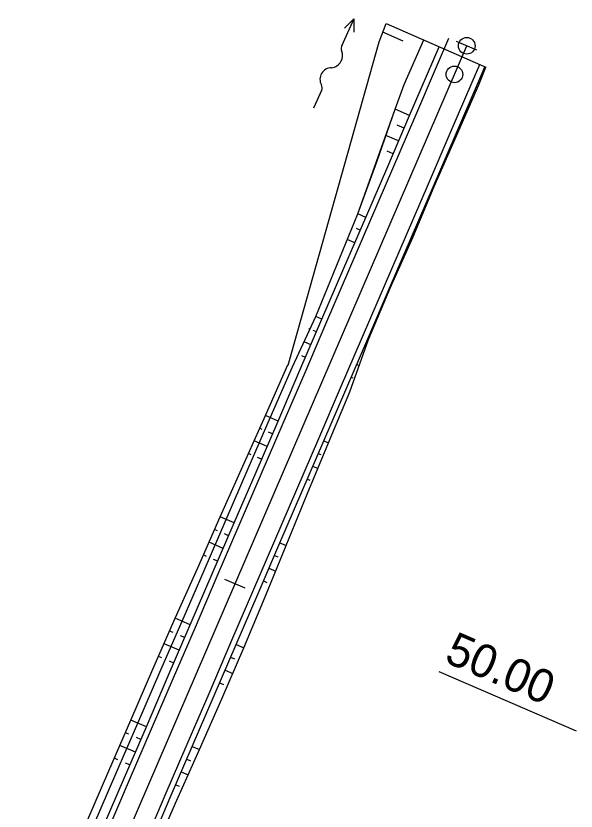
# Model space of a CAD drawing. Extents: x -481645 to -478728, y -1113199 to -1110710.
# Drawn here: x -480117.1 to -480066.6, y -1112436.3 to -1112364.6 of the extents above; entities that cross this region are included whole.
import ezdxf

# ---------------------------------------------------------------- set-up
doc = ezdxf.new("R2010")
doc.units = 0
for name, color, linetype in [('CP14_HECTOMETRY', 7, 'Continuous'), ('CP14_HLBODY', 7, 'Continuous'), ('Vrstva 52', 7, 'Continuous'), ('Vrstva 53', 7, 'Continuous'), ('Vrstva 54', 7, 'Continuous'), ('Vrstva 55', 7, 'Continuous'), ('Vrstva 56', 7, 'Continuous'), ('Vrstva 57', 7, 'Continuous'), ('Vrstva 58', 7, 'Continuous'), ('Vrstva 59', 7, 'Continuous'), ('Vrstva 60', 7, 'Continuous'), ('Vrstva 61', 7, 'Continuous'), ('Vrstva 62', 7, 'Continuous')]:
    doc.layers.add(name, color=color, linetype=linetype)

# ---------------------------------------------------------------- blocks, each defined once
blk = doc.blocks.new('A$C70B')
at = {"layer": 'CP14_HLBODY'}
for p, q in [((0.869, 0.002), (-0.869, -0.002)), ((6.861, 0.426), (7.971, -0.002)), ((7.971, -0.002), (5.275, -0.002)), ((7.971, -0.002), (6.862, -0.478))]:
    blk.add_line(p, q, dxfattribs=at)
for centre, radius, start, end in [((0.872, 0.584), 0.582, 269.69241, 322.79009), ((2.168, -0.416), 1.055, 24.40393, 142.08362), ((4.08, 0.589), 1.109, 210.88731, 317.37071), ((5.319, -0.636), 0.636, 85.97658, 131.72478)]:
    blk.add_arc(centre, radius, start, end, dxfattribs=at)

msp = doc.modelspace()

# ---------------------------------------------------------------- linework, layer by layer
at = {"layer": 'Vrstva 52'}
msp.add_line((-480117.117, -1112461.699), (-480076.44, -1112367.31), dxfattribs=at)
at = {"layer": 'Vrstva 53'}
for p, q in [((-480084.346, -1112366.961), (-480083.701, -1112365.308)), ((-480084.345, -1112366.962), (-480083.7, -1112365.308)), ((-480083.7, -1112365.308), (-480074.708, -1112369.248)), ((-480092.564, -1112396.087), (-480084.345, -1112366.962)), ((-480075.357, -1112370.835), (-480074.708, -1112369.248)), ((-480077.359, -1112375.417), (-480075.357, -1112370.835)), ((-480086.281, -1112382.461), (-480082.906, -1112373.026)), ((-480084.564, -1112377.756), (-480082.906, -1112373.026)), ((-480079.392, -1112379.985), (-480077.359, -1112375.417)), ((-480086.281, -1112382.461), (-480084.564, -1112377.756)), ((-480081.303, -1112384.606), (-480079.392, -1112379.985)), ((-480088.162, -1112387.095), (-480086.281, -1112382.461)), ((-480088.162, -1112387.095), (-480086.281, -1112382.461)), ((-480083.344, -1112389.171), (-480081.303, -1112384.606)), ((-480090.068, -1112391.718), (-480088.162, -1112387.095)), ((-480090.068, -1112391.718), (-480088.162, -1112387.095)), ((-480085.299, -1112393.773), (-480083.344, -1112389.171)), ((-480086.981, -1112398.493), (-480085.299, -1112393.773)), ((-480094.609, -1112400.65), (-480092.575, -1112396.082)), ((-480088.911, -1112403.106), (-480086.981, -1112398.493)), ((-480096.643, -1112405.218), (-480094.609, -1112400.65)), ((-480090.832, -1112407.722), (-480088.911, -1112403.106)), ((-480098.678, -1112409.785), (-480096.643, -1112405.218)), ((-480092.728, -1112412.35), (-480090.832, -1112407.722)), ((-480100.712, -1112414.354), (-480098.678, -1112409.785)), ((-480094.625, -1112416.976), (-480092.728, -1112412.35)), ((-480102.746, -1112418.921), (-480100.712, -1112414.354)), ((-480096.567, -1112421.584), (-480094.625, -1112416.976)), ((-480104.756, -1112423.499), (-480102.746, -1112418.921)), ((-480098.543, -1112426.177), (-480096.567, -1112421.584)), ((-480106.733, -1112428.092), (-480104.756, -1112423.499)), ((-480100.542, -1112430.76), (-480098.543, -1112426.177)), ((-480108.719, -1112432.681), (-480106.733, -1112428.092)), ((-480102.582, -1112435.326), (-480100.542, -1112430.76)), ((-480110.705, -1112437.27), (-480108.719, -1112432.681)), ((-480104.622, -1112439.891), (-480102.582, -1112435.326))]:
    msp.add_line(p, q, dxfattribs=at)
at = {"layer": 'Vrstva 54'}
for p, q in [((-480082.089, -1112370.811), (-480080.326, -1112366.786)), ((-480082.906, -1112373.026), (-480082.089, -1112370.811)), ((-480092.172, -1112396.255), (-480090.068, -1112391.718)), ((-480092.165, -1112396.258), (-480090.068, -1112391.718)), ((-480094.163, -1112400.842), (-480092.172, -1112396.255)), ((-480096.154, -1112405.428), (-480094.163, -1112400.842)), ((-480098.145, -1112410.015), (-480096.154, -1112405.428)), ((-480100.136, -1112414.601), (-480098.145, -1112410.015)), ((-480102.127, -1112419.188), (-480100.136, -1112414.601)), ((-480104.118, -1112423.775), (-480102.127, -1112419.188)), ((-480106.109, -1112428.361), (-480104.118, -1112423.775)), ((-480108.1, -1112432.948), (-480106.109, -1112428.361)), ((-480110.091, -1112437.534), (-480108.1, -1112432.948))]:
    msp.add_line(p, q, dxfattribs=at)
at = {"layer": 'Vrstva 55'}
for p, q in [((-480081.597, -1112373.59), (-480078.928, -1112367.399)), ((-480079.618, -1112368.999), (-480079.486, -1112368.692)), ((-480075.485, -1112370.78), (-480074.806, -1112369.204)), ((-480077.464, -1112375.371), (-480075.485, -1112370.78)), ((-480083.575, -1112378.182), (-480081.597, -1112373.59)), ((-480079.443, -1112379.963), (-480077.464, -1112375.371)), ((-480085.554, -1112382.774), (-480083.575, -1112378.182)), ((-480081.422, -1112384.555), (-480079.443, -1112379.963)), ((-480087.533, -1112387.366), (-480085.554, -1112382.774)), ((-480083.4, -1112389.147), (-480081.422, -1112384.555)), ((-480089.512, -1112391.957), (-480087.533, -1112387.366)), ((-480085.379, -1112393.738), (-480083.4, -1112389.147)), ((-480091.491, -1112396.549), (-480089.512, -1112391.957)), ((-480087.358, -1112398.33), (-480085.379, -1112393.738)), ((-480093.469, -1112401.141), (-480091.491, -1112396.549)), ((-480089.337, -1112402.922), (-480087.358, -1112398.33)), ((-480095.448, -1112405.733), (-480093.469, -1112401.141)), ((-480091.316, -1112407.514), (-480089.337, -1112402.922)), ((-480097.427, -1112410.324), (-480095.448, -1112405.733)), ((-480093.294, -1112412.105), (-480091.316, -1112407.514)), ((-480099.406, -1112414.916), (-480097.427, -1112410.324)), ((-480095.273, -1112416.697), (-480093.294, -1112412.105)), ((-480101.385, -1112419.508), (-480099.406, -1112414.916)), ((-480097.252, -1112421.289), (-480095.273, -1112416.697)), ((-480103.364, -1112424.1), (-480101.385, -1112419.508)), ((-480099.231, -1112425.881), (-480097.252, -1112421.289)), ((-480105.342, -1112428.692), (-480103.364, -1112424.1)), ((-480101.21, -1112430.472), (-480099.231, -1112425.881)), ((-480107.321, -1112433.283), (-480105.342, -1112428.692)), ((-480103.189, -1112435.064), (-480101.21, -1112430.472)), ((-480109.3, -1112437.875), (-480107.321, -1112433.283)), ((-480105.167, -1112439.656), (-480103.189, -1112435.064))]:
    msp.add_line(p, q, dxfattribs=at)
at = {"layer": 'Vrstva 56'}
for p, q in [((-480079.159, -1112369.196), (-480078.05, -1112366.625)), ((-480081.137, -1112373.788), (-480079.159, -1112369.196)), ((-480075.944, -1112370.582), (-480075.264, -1112369.004)), ((-480077.923, -1112375.173), (-480075.944, -1112370.582)), ((-480083.116, -1112378.38), (-480081.137, -1112373.788)), ((-480079.902, -1112379.765), (-480077.923, -1112375.173)), ((-480085.095, -1112382.972), (-480083.116, -1112378.38)), ((-480081.881, -1112384.357), (-480079.902, -1112379.765)), ((-480087.074, -1112387.564), (-480085.095, -1112382.972)), ((-480083.86, -1112388.949), (-480081.881, -1112384.357)), ((-480089.053, -1112392.155), (-480087.074, -1112387.564)), ((-480085.838, -1112393.54), (-480083.86, -1112388.949)), ((-480091.031, -1112396.747), (-480089.053, -1112392.155)), ((-480087.817, -1112398.132), (-480085.838, -1112393.54)), ((-480093.01, -1112401.339), (-480091.031, -1112396.747)), ((-480089.796, -1112402.724), (-480087.817, -1112398.132)), ((-480094.989, -1112405.931), (-480093.01, -1112401.339)), ((-480091.775, -1112407.316), (-480089.796, -1112402.724)), ((-480096.968, -1112410.522), (-480094.989, -1112405.931)), ((-480093.754, -1112411.908), (-480091.775, -1112407.316)), ((-480098.947, -1112415.114), (-480096.968, -1112410.522)), ((-480095.732, -1112416.499), (-480093.754, -1112411.908)), ((-480100.926, -1112419.706), (-480098.947, -1112415.114)), ((-480097.711, -1112421.091), (-480095.732, -1112416.499)), ((-480102.904, -1112424.298), (-480100.926, -1112419.706)), ((-480099.69, -1112425.683), (-480097.711, -1112421.091)), ((-480104.883, -1112428.889), (-480102.904, -1112424.298)), ((-480101.669, -1112430.275), (-480099.69, -1112425.683)), ((-480106.862, -1112433.481), (-480104.883, -1112428.889)), ((-480103.648, -1112434.866), (-480101.669, -1112430.275)), ((-480108.841, -1112438.073), (-480106.862, -1112433.481)), ((-480105.627, -1112439.458), (-480103.648, -1112434.866))]:
    msp.add_line(p, q, dxfattribs=at)
at = {"layer": 'Vrstva 57'}
for p, q in [((-480079.159, -1112369.196), (-480078.05, -1112366.625)), ((-480081.137, -1112373.788), (-480079.159, -1112369.196)), ((-480075.944, -1112370.582), (-480075.264, -1112369.004)), ((-480077.923, -1112375.173), (-480075.944, -1112370.582)), ((-480083.116, -1112378.38), (-480081.137, -1112373.788)), ((-480079.902, -1112379.765), (-480077.923, -1112375.173)), ((-480085.095, -1112382.972), (-480083.116, -1112378.38)), ((-480081.881, -1112384.357), (-480079.902, -1112379.765)), ((-480087.074, -1112387.564), (-480085.095, -1112382.972)), ((-480083.86, -1112388.949), (-480081.881, -1112384.357)), ((-480089.053, -1112392.155), (-480087.074, -1112387.564)), ((-480085.838, -1112393.54), (-480083.86, -1112388.949)), ((-480091.031, -1112396.747), (-480089.053, -1112392.155)), ((-480087.817, -1112398.132), (-480085.838, -1112393.54)), ((-480093.01, -1112401.339), (-480091.031, -1112396.747)), ((-480089.796, -1112402.724), (-480087.817, -1112398.132)), ((-480094.989, -1112405.931), (-480093.01, -1112401.339)), ((-480091.775, -1112407.316), (-480089.796, -1112402.724)), ((-480096.968, -1112410.522), (-480094.989, -1112405.931)), ((-480093.754, -1112411.908), (-480091.775, -1112407.316)), ((-480098.947, -1112415.114), (-480096.968, -1112410.522)), ((-480095.732, -1112416.499), (-480093.754, -1112411.908)), ((-480100.926, -1112419.706), (-480098.947, -1112415.114)), ((-480097.711, -1112421.091), (-480095.732, -1112416.499)), ((-480102.904, -1112424.298), (-480100.926, -1112419.706)), ((-480099.69, -1112425.683), (-480097.711, -1112421.091)), ((-480104.883, -1112428.889), (-480102.904, -1112424.298)), ((-480101.669, -1112430.275), (-480099.69, -1112425.683)), ((-480106.862, -1112433.481), (-480104.883, -1112428.889)), ((-480103.648, -1112434.866), (-480101.669, -1112430.275)), ((-480108.841, -1112438.073), (-480106.862, -1112433.481)), ((-480105.627, -1112439.458), (-480103.648, -1112434.866))]:
    msp.add_line(p, q, dxfattribs=at)
at = {"layer": 'Vrstva 58'}
for p, q in [((-480075.525, -1112367.713), (-480077.362, -1112366.922)), ((-480096.421, -1112416.202), (-480098.258, -1112415.411)), ((-480078.973, -1112423.722), (-480066.575, -1112429.065))]:
    msp.add_line(p, q, dxfattribs=at)
at = {"layer": 'Vrstva 59'}
msp.add_circle((-480076.44, -1112367.31), 0.75, dxfattribs=at)
at = {"layer": 'Vrstva 60'}
msp.add_circle((-480077.551, -1112369.889), 0.75, dxfattribs=at)
at = {"layer": 'Vrstva 61'}
for p, q in [((-480082.17, -1112366.882), (-480084.006, -1112366.091)), ((-480082.169, -1112366.882), (-480084.005, -1112366.091)), ((-480081.597, -1112373.59), (-480082.906, -1112373.026)), ((-480083.321, -1112374.208), (-480083.321, -1112374.208)), ((-480082.091, -1112374.738), (-480082.706, -1112374.473)), ((-480082.586, -1112375.886), (-480083.735, -1112375.391)), ((-480084.15, -1112376.574), (-480084.15, -1112376.574)), ((-480083.081, -1112377.034), (-480083.616, -1112376.804)), ((-480085.554, -1112382.774), (-480086.281, -1112382.461)), ((-480086.751, -1112383.619), (-480086.751, -1112383.619)), ((-480086.049, -1112383.922), (-480086.4, -1112383.77)), ((-480086.544, -1112385.07), (-480087.222, -1112384.778)), ((-480089.512, -1112391.957), (-480090.068, -1112391.718)), ((-480090.644, -1112392.83), (-480090.694, -1112392.809)), ((-480090.007, -1112393.105), (-480090.301, -1112392.978)), ((-480090.501, -1112394.253), (-480091.12, -1112393.987)), ((-480090.996, -1112395.401), (-480091.321, -1112395.261)), ((-480093.469, -1112401.141), (-480094.609, -1112400.65)), ((-480094.889, -1112401.89), (-480095.117, -1112401.792)), ((-480093.964, -1112402.289), (-480094.312, -1112402.139)), ((-480094.459, -1112403.437), (-480095.626, -1112402.934)), ((-480095.896, -1112404.179), (-480096.134, -1112404.076)), ((-480094.954, -1112404.585), (-480095.306, -1112404.434)), ((-480097.427, -1112410.324), (-480098.678, -1112409.785)), ((-480098.915, -1112411.044), (-480099.187, -1112410.927)), ((-480097.922, -1112411.472), (-480098.282, -1112411.317)), ((-480098.416, -1112412.62), (-480099.695, -1112412.069)), ((-480099.921, -1112413.333), (-480100.203, -1112413.211)), ((-480098.911, -1112413.768), (-480099.275, -1112413.612)), ((-480101.385, -1112419.508), (-480102.746, -1112418.921)), ((-480102.937, -1112420.2), (-480103.249, -1112420.066)), ((-480101.879, -1112420.656), (-480102.252, -1112420.496)), ((-480102.374, -1112421.804), (-480103.751, -1112421.21)), ((-480103.938, -1112422.492), (-480104.254, -1112422.355)), ((-480102.869, -1112422.952), (-480103.245, -1112422.79)), ((-480105.342, -1112428.692), (-480106.733, -1112428.092)), ((-480106.918, -1112429.374), (-480107.229, -1112429.239)), ((-480105.837, -1112429.839), (-480106.222, -1112429.674)), ((-480106.332, -1112430.987), (-480107.726, -1112430.387)), ((-480107.912, -1112431.668), (-480108.222, -1112431.534)), ((-480106.826, -1112432.135), (-480107.214, -1112431.968))]:
    msp.add_line(p, q, dxfattribs=at)
at = {"layer": 'Vrstva 62'}
for p, q in [((-480075.116, -1112369.922), (-480075.06, -1112369.946)), ((-480075.004, -1112369.971), (-480075.004, -1112369.971)), ((-480077.464, -1112375.371), (-480077.359, -1112375.417)), ((-480077.959, -1112376.519), (-480077.913, -1112376.539)), ((-480077.867, -1112376.559), (-480077.867, -1112376.559)), ((-480078.453, -1112377.667), (-480078.376, -1112377.701)), ((-480078.948, -1112378.815), (-480078.916, -1112378.829)), ((-480078.884, -1112378.843), (-480078.884, -1112378.843)), ((-480081.422, -1112384.555), (-480081.303, -1112384.606)), ((-480081.916, -1112385.703), (-480081.864, -1112385.725)), ((-480081.813, -1112385.747), (-480081.813, -1112385.747)), ((-480082.411, -1112386.851), (-480082.323, -1112386.888)), ((-480082.906, -1112387.999), (-480082.87, -1112388.014)), ((-480082.834, -1112388.03), (-480082.834, -1112388.03)), ((-480085.379, -1112393.738), (-480085.299, -1112393.773)), ((-480085.874, -1112394.886), (-480085.797, -1112394.92)), ((-480085.72, -1112394.953), (-480085.72, -1112394.953)), ((-480086.369, -1112396.034), (-480086.14, -1112396.133)), ((-480086.863, -1112397.182), (-480086.712, -1112397.248)), ((-480086.561, -1112397.313), (-480086.561, -1112397.313)), ((-480089.337, -1112402.922), (-480088.911, -1112403.106)), ((-480089.832, -1112404.07), (-480089.612, -1112404.165)), ((-480089.391, -1112404.26), (-480089.391, -1112404.26)), ((-480090.326, -1112405.218), (-480089.871, -1112405.414)), ((-480090.821, -1112406.366), (-480090.586, -1112406.467)), ((-480090.351, -1112406.568), (-480090.351, -1112406.568)), ((-480093.294, -1112412.105), (-480092.728, -1112412.35)), ((-480093.789, -1112413.253), (-480093.495, -1112413.38)), ((-480093.202, -1112413.506), (-480093.202, -1112413.506)), ((-480094.284, -1112414.401), (-480093.677, -1112414.663)), ((-480094.779, -1112415.549), (-480094.465, -1112415.684)), ((-480094.151, -1112415.82), (-480094.151, -1112415.82)), ((-480097.252, -1112421.289), (-480096.567, -1112421.584)), ((-480097.747, -1112422.437), (-480097.404, -1112422.584)), ((-480097.061, -1112422.732), (-480097.061, -1112422.732)), ((-480098.242, -1112423.585), (-480097.555, -1112423.881)), ((-480098.736, -1112424.733), (-480098.392, -1112424.881)), ((-480098.049, -1112425.029), (-480098.049, -1112425.029)), ((-480101.21, -1112430.472), (-480100.542, -1112430.76)), ((-480101.704, -1112431.62), (-480101.378, -1112431.761)), ((-480101.052, -1112431.902), (-480101.052, -1112431.902)), ((-480102.199, -1112432.768), (-480101.562, -1112433.043)), ((-480102.694, -1112433.916), (-480102.383, -1112434.05)), ((-480102.072, -1112434.184), (-480102.072, -1112434.184))]:
    msp.add_line(p, q, dxfattribs=at)

# ---------------------------------------------------------------- block references
at = {"layer": 'CP14_HECTOMETRY', "rotation": 65.74340576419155}
msp.add_blockref('A$C70B', (-480089.897, -1112372.145), dxfattribs=at)

# ---------------------------------------------------------------- texts
at = {"layer": 'Vrstva 58'}
msp.add_text('50.00', height=3, rotation=336.68644, dxfattribs=at).set_placement((-480078.578, -1112422.803))

doc.saveas('drawing.dxf')
